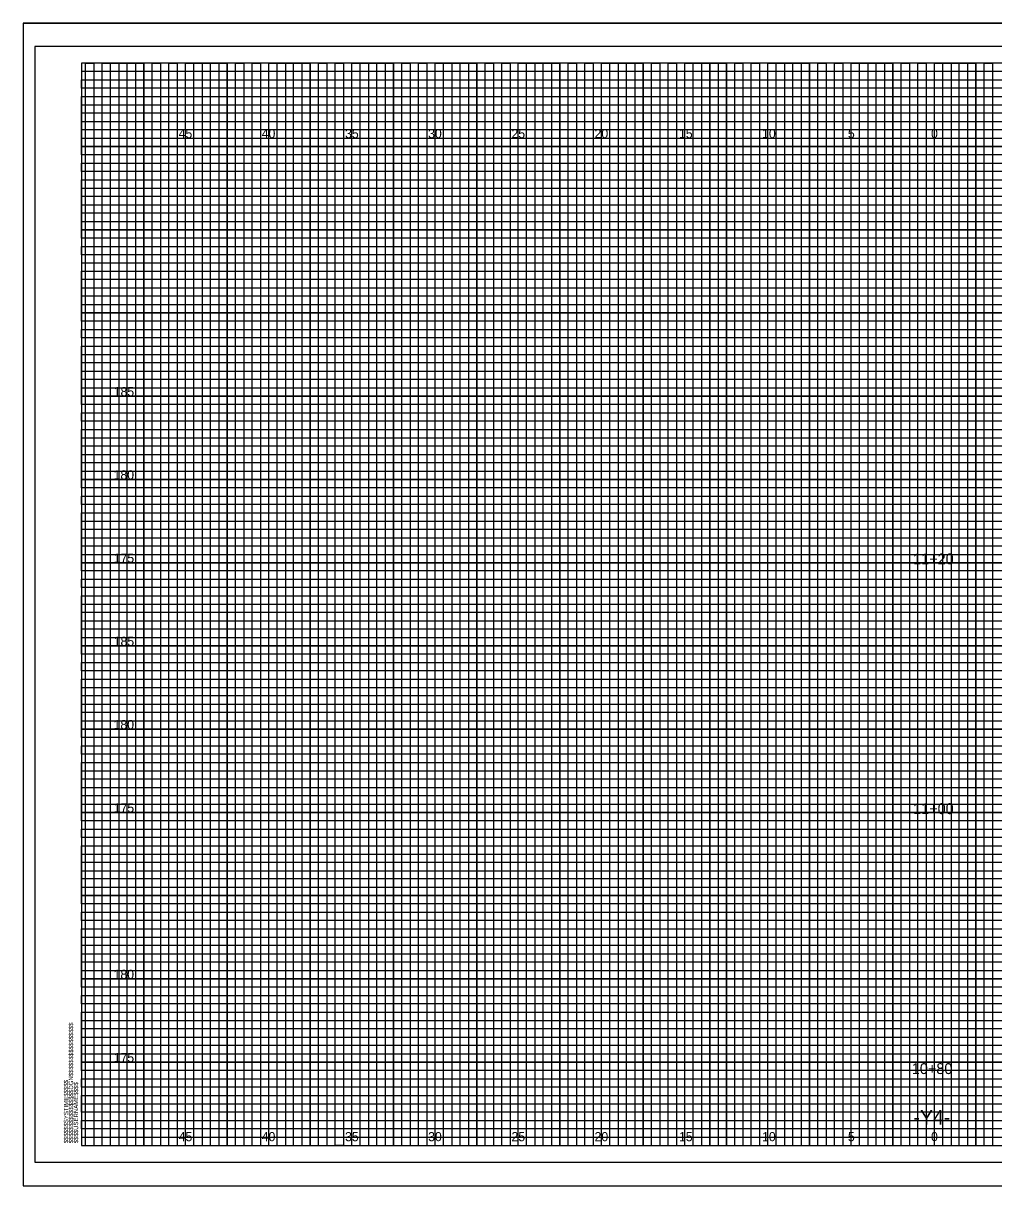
# Model space of a CAD drawing. Extents: x -4 to 103, y -2 to 138.
# Drawn here: x -3.5 to 54.8, y 68.4 to 138.2 of the extents above; entities that cross this region are included whole.
import ezdxf

# ---------------------------------------------------------------- set-up
doc = ezdxf.new("R2010")
doc.units = 0
for name, color, linetype in [('Old_Level_10', 7, 'Continuous'), ('Old_Level_3', 7, 'Continuous'), ('Old_Level_4', 7, 'Continuous'), ('Old_Level_5', 7, 'Continuous'), ('Old_Level_8', 7, 'Continuous'), ('Prop XS Dump Level', 7, 'Continuous'), ('Prop XS Elevation Labels', 7, 'Continuous'), ('Prop XS EOT Tick Mark', 7, 'Continuous'), ('Prop XS Finish Grade', 7, 'Continuous'), ('Prop XS Finish Grade Pavement', 7, 'Continuous'), ('Prop XS Subgrade Concrete', 7, 'Continuous')]:
    doc.layers.add(name, color=color, linetype=linetype)

msp = doc.modelspace()

# ---------------------------------------------------------------- linework, layer by layer
at = {"layer": 'Old_Level_10'}
for p, q in [((1.25, 70.825), (1.25, 135.825)), ((3.75, 70.825), (3.75, 135.825)), ((6.25, 70.825), (6.25, 135.825)), ((8.75, 70.825), (8.75, 135.825)), ((11.25, 70.825), (11.25, 135.825)), ((13.75, 70.825), (13.75, 135.825)), ((16.25, 70.825), (16.25, 135.825)), ((18.75, 70.825), (18.75, 135.825)), ((21.25, 70.825), (21.25, 135.825)), ((23.75, 70.825), (23.75, 135.825)), ((26.25, 70.825), (26.25, 135.825)), ((28.75, 70.825), (28.75, 135.825)), ((31.25, 70.825), (31.25, 135.825)), ((33.75, 70.825), (33.75, 135.825)), ((36.25, 70.825), (36.25, 135.825)), ((38.75, 70.825), (38.75, 135.825)), ((41.25, 70.825), (41.25, 135.825)), ((43.75, 70.825), (43.75, 135.825)), ((46.25, 70.825), (46.25, 135.825)), ((48.75, 70.825), (48.75, 135.825)), ((51.25, 70.825), (51.25, 135.825)), ((53.75, 70.825), (53.75, 135.825)), ((0, 133.325), (74.25, 133.325)), ((0, 130.825), (102.5, 130.825)), ((0, 128.325), (102.5, 128.325)), ((0, 125.825), (102.5, 125.825)), ((0, 123.325), (102.5, 123.325)), ((0, 120.825), (102.5, 120.825)), ((0, 118.325), (102.5, 118.325)), ((0, 115.825), (102.5, 115.825)), ((0, 113.325), (102.5, 113.325)), ((0, 110.825), (102.5, 110.825)), ((0, 108.325), (102.5, 108.325)), ((0, 105.825), (102.5, 105.825)), ((0, 103.325), (102.5, 103.325)), ((0, 100.825), (102.5, 100.825)), ((0, 98.325), (102.5, 98.325)), ((0, 95.825), (102.5, 95.825)), ((0, 93.325), (102.5, 93.325)), ((0, 90.825), (102.5, 90.825)), ((0, 88.325), (102.5, 88.325)), ((0, 85.825), (102.5, 85.825)), ((0, 83.325), (102.5, 83.325)), ((0, 80.825), (102.5, 80.825)), ((0, 78.325), (102.5, 78.325)), ((0, 75.825), (102.5, 75.825)), ((0, 73.325), (102.5, 73.325))]:
    msp.add_line(p, q, dxfattribs=at)
at = {"layer": 'Old_Level_3'}
for p, q in [((-3.5, 138.225), (103.4, 138.225)), ((-3.5, 138.225), (-3.5, 68.4)), ((-3.5, 68.4), (103.4, 68.4))]:
    msp.add_line(p, q, dxfattribs=at)
at = {"layer": 'Old_Level_4'}
msp.add_lwpolyline([(103, 136.825), (-2.8, 136.825), (-2.8, 69.825), (103, 69.825)], close=True, dxfattribs=at)
at = {"layer": 'Old_Level_5'}
msp.add_lwpolyline([(103.4, 138.225), (-3.5, 138.225), (-3.5, 68.4), (103.4, 68.4)], close=True, dxfattribs=at)
at = {"layer": 'Old_Level_8'}
for points in [[(1.25, 70.825), (1.25, 135.825), (3.75, 135.825), (3.75, 70.825), (6.25, 70.825), (6.25, 135.825), (8.75, 135.825), (8.75, 70.825), (11.25, 70.825), (11.25, 135.825), (13.75, 135.825), (13.75, 70.825), (16.25, 70.825), (16.25, 135.825), (18.75, 135.825), (18.75, 70.825), (21.25, 70.825), (21.25, 135.825), (23.75, 135.825), (23.75, 70.825), (26.25, 70.825), (26.25, 135.825), (28.75, 135.825), (28.75, 70.825), (31.25, 70.825), (31.25, 135.825), (33.75, 135.825), (33.75, 70.825), (36.25, 70.825), (36.25, 135.825), (38.75, 135.825), (38.75, 70.825), (41.25, 70.825), (41.25, 135.825), (43.75, 135.825), (43.75, 70.825), (46.25, 70.825), (46.25, 135.825), (48.75, 135.825), (48.75, 70.825), (51.25, 70.825), (51.25, 135.825), (53.75, 135.825), (53.75, 70.825)], [(102.5, 130.825), (0, 130.825), (0, 133.325), (74.25, 133.325)], [(102.5, 125.825), (0, 125.825), (0, 128.325), (102.5, 128.325)], [(102.5, 120.825), (0, 120.825), (0, 123.325), (102.5, 123.325)], [(102.5, 115.825), (0, 115.825), (0, 118.325), (102.5, 118.325)], [(102.5, 110.825), (0, 110.825), (0, 113.325), (102.5, 113.325)], [(102.5, 105.825), (0, 105.825), (0, 108.325), (102.5, 108.325)], [(102.5, 100.825), (0, 100.825), (0, 103.325), (102.5, 103.325)], [(102.5, 95.825), (0, 95.825), (0, 98.325), (102.5, 98.325)], [(102.5, 90.825), (0, 90.825), (0, 93.325), (102.5, 93.325)], [(102.5, 85.825), (0, 85.825), (0, 88.325), (102.5, 88.325)], [(102.5, 80.825), (0, 80.825), (0, 83.325), (102.5, 83.325)], [(102.5, 75.825), (0, 75.825), (0, 78.325), (102.5, 78.325)], [(0, 73.325), (102.5, 73.325)]]:
    msp.add_lwpolyline(points, dxfattribs=at)
at = {"layer": 'Prop XS Elevation Labels'}
msp.add_lwpolyline([(102.5, 135.825), (0, 135.825), (0, 70.825), (102.5, 70.825)], close=True, dxfattribs=at)
at = {"layer": 'Prop XS Finish Grade'}
for points in [[(0.25, 70.825), (0.25, 135.825), (0.75, 135.825), (0.75, 70.825), (1.75, 70.825), (1.75, 135.825), (2.25, 135.825), (2.25, 70.825), (2.75, 70.825), (2.75, 135.825), (3.25, 135.825), (3.25, 70.825), (4.25, 70.825), (4.25, 135.825), (4.75, 135.825), (4.75, 70.825), (5.25, 70.825), (5.25, 135.825), (5.75, 135.825), (5.75, 70.825), (6.75, 70.825), (6.75, 135.825), (7.25, 135.825), (7.25, 70.825), (7.75, 70.825), (7.75, 135.825), (8.25, 135.825), (8.25, 70.825), (9.25, 70.825), (9.25, 135.825), (9.75, 135.825), (9.75, 70.825), (10.25, 70.825), (10.25, 135.825), (10.75, 135.825), (10.75, 70.825), (11.75, 70.825), (11.75, 135.825), (12.25, 135.825), (12.25, 70.825), (12.75, 70.825), (12.75, 135.825), (13.25, 135.825), (13.25, 70.825), (14.25, 70.825), (14.25, 135.825), (14.75, 135.825), (14.75, 70.825), (15.75, 70.825), (15.25, 70.825), (15.25, 135.825), (15.75, 135.825), (15.75, 70.825), (16.75, 70.825), (16.75, 135.825), (17.25, 135.825), (17.25, 70.825), (17.75, 70.825), (17.75, 135.825), (18.25, 135.825), (18.25, 70.825), (19.25, 70.825), (19.25, 135.825), (19.75, 135.825), (19.75, 70.825), (20.25, 70.825), (20.25, 135.825), (20.75, 135.825), (20.75, 70.825), (21.75, 70.825), (21.75, 135.825), (22.25, 135.825), (22.25, 70.825), (22.75, 70.825), (22.75, 135.825), (23.25, 135.825), (23.25, 70.825), (24.25, 70.825), (24.25, 135.825), (24.75, 135.825), (24.75, 70.825), (25.25, 70.825), (25.25, 135.825), (25.75, 135.825), (25.75, 70.825), (26.75, 70.825), (26.75, 135.825), (27.25, 135.825), (27.25, 70.825), (27.75, 70.825), (27.75, 135.825), (28.25, 135.825), (28.25, 70.825), (29.25, 70.825), (29.25, 135.825), (29.75, 135.825), (29.75, 70.825), (30.25, 70.825), (30.25, 135.825), (30.75, 135.825), (30.75, 70.825)], [(30.75, 70.825), (31.75, 70.825), (31.75, 135.825), (32.25, 135.825), (32.25, 70.825), (32.75, 70.825), (32.75, 135.825), (33.25, 135.825), (33.25, 70.825), (34.25, 70.825), (34.25, 135.825), (34.75, 135.825), (34.75, 70.825), (35.25, 70.825), (35.25, 135.825), (35.75, 135.825), (35.75, 70.825), (36.75, 70.825), (36.75, 135.825), (37.25, 135.825), (37.25, 70.825), (37.75, 70.825), (37.75, 135.825), (37.75, 70.825)], [(38.25, 135.825), (38.25, 70.825), (39.25, 70.825), (39.25, 135.825), (39.75, 135.825), (39.75, 70.825), (40.25, 70.825), (40.25, 135.825), (40.75, 135.825), (40.75, 70.825), (41.75, 70.825), (41.75, 135.825), (42.25, 135.825), (42.25, 70.825), (42.75, 70.825), (42.75, 135.825), (43.25, 135.825), (43.25, 70.825), (43.75, 70.825), (44.25, 70.825), (44.25, 135.825), (44.75, 135.825), (44.75, 70.825), (45.25, 70.825), (45.25, 135.825), (45.75, 135.825), (45.75, 70.825), (46.75, 70.825), (46.75, 135.825), (47.25, 135.825), (47.25, 70.825), (47.75, 70.825), (47.75, 135.825), (48.25, 135.825), (48.25, 70.825), (49.25, 70.825), (49.25, 135.825), (49.75, 135.825), (49.75, 70.825), (50.25, 70.825), (50.25, 135.825), (50.75, 135.825), (50.75, 70.825), (51.75, 70.825), (51.75, 135.825), (52.25, 135.825), (52.25, 70.825), (52.75, 70.825), (52.75, 135.825), (53.25, 135.825), (53.25, 70.825), (54.25, 70.825), (54.25, 135.825), (54.75, 135.825), (54.75, 70.825), (55.25, 70.825)], [(0, 132.825), (0, 133.825), (74.25, 133.825), (74.25, 134.325), (0, 134.325), (0, 134.825), (74.25, 134.825), (74.25, 135.325), (0, 135.325)], [(102.5, 132.825), (0, 132.825)], [(102.5, 131.825), (0, 131.825), (0, 132.325), (102.5, 132.325)], [(102.5, 130.325), (0, 130.325), (0, 131.325), (102.5, 131.325)], [(102.5, 129.325), (0, 129.325), (0, 129.825), (102.5, 129.825)], [(102.5, 127.825), (0, 127.825), (0, 128.825), (102.5, 128.825)], [(102.5, 126.825), (0, 126.825), (0, 127.325), (102.5, 127.325)], [(102.5, 125.325), (0, 125.325), (0, 126.325), (102.5, 126.325)], [(102.5, 124.325), (0, 124.325), (0, 124.825), (102.5, 124.825)], [(0, 123.825), (102.5, 123.825)], [(102.5, 122.825), (0, 122.825)], [(102.5, 121.825), (0, 121.825), (0, 122.325), (102.5, 122.325)], [(102.5, 120.325), (0, 120.325), (0, 121.325), (102.5, 121.325)], [(102.5, 119.325), (0, 119.325), (0, 119.825), (102.5, 119.825)], [(102.5, 117.825), (0, 117.825), (0, 118.825), (102.5, 118.825)], [(102.5, 116.825), (0, 116.825), (0, 117.325), (102.5, 117.325)], [(102.5, 115.325), (0, 115.325), (0, 116.325), (102.5, 116.325)], [(102.5, 114.325), (0, 114.325), (0, 114.825), (102.5, 114.825)], [(102.5, 112.825), (0, 112.825), (0, 113.825), (102.5, 113.825)], [(102.5, 111.825), (0, 111.825), (0, 112.325), (102.5, 112.325)], [(102.5, 110.325), (0, 110.325), (0, 111.325), (102.5, 111.325)], [(102.5, 109.325), (0, 109.325), (0, 109.825), (102.5, 109.825)], [(102.5, 107.825), (0, 107.825), (0, 108.825), (102.5, 108.825)], [(102.5, 106.825), (0, 106.825), (0, 107.325), (102.5, 107.325)], [(102.5, 105.325), (0, 105.325), (0, 106.325), (102.5, 106.325)], [(102.5, 104.325), (0, 104.325), (0, 104.825), (102.5, 104.825)], [(102.5, 102.825), (0, 102.825), (0, 103.825), (102.5, 103.825)], [(102.5, 101.825), (0, 101.825), (0, 102.325)], [(0, 102.325), (102.5, 102.325)], [(102.5, 100.325), (0, 100.325), (0, 101.325), (102.5, 101.325)], [(102.5, 99.325), (0, 99.325), (0, 99.825), (102.5, 99.825)], [(102.5, 97.825), (0, 97.825), (0, 98.825), (102.5, 98.825)], [(102.5, 96.825), (0, 96.825), (0, 97.325), (102.5, 97.325)], [(102.5, 95.325), (0, 95.325), (0, 96.325), (102.5, 96.325)], [(102.5, 94.325), (0, 94.325), (0, 94.825), (102.5, 94.825)], [(102.5, 92.825), (0, 92.825), (0, 93.825), (102.5, 93.825)], [(102.5, 91.825), (0, 91.825), (0, 92.325), (102.5, 92.325)], [(102.5, 90.325), (0, 90.325), (0, 91.325), (102.5, 91.325)], [(102.5, 89.325), (0, 89.325), (0, 89.825), (102.5, 89.825)], [(102.5, 87.825), (0, 87.825), (0, 88.825), (102.5, 88.825)], [(102.5, 86.825), (0, 86.825), (0, 87.325), (102.5, 87.325)], [(102.5, 85.325), (0, 85.325), (0, 86.325), (102.5, 86.325)], [(102.5, 84.325), (0, 84.325), (0, 84.825), (102.5, 84.825)], [(102.5, 82.825), (0, 82.825), (0, 83.825), (102.5, 83.825)], [(102.5, 81.825), (0, 81.825), (0, 82.325), (102.5, 82.325)], [(102.5, 80.325), (0, 80.325), (0, 81.325), (102.5, 81.325)], [(102.5, 79.325), (0, 79.325), (0, 79.825), (102.5, 79.825)], [(102.5, 77.825), (0, 77.825), (0, 78.825), (102.5, 78.825)], [(102.5, 76.825), (0, 76.825), (0, 77.325), (102.5, 77.325)], [(102.5, 75.325), (0, 75.325), (0, 76.325), (102.5, 76.325)], [(102.5, 74.325), (0, 74.325), (0, 74.825), (102.5, 74.825)], [(102.5, 72.825), (0, 72.825), (0, 73.825), (102.5, 73.825)], [(102.5, 71.825), (0, 71.825), (0, 72.325), (102.5, 72.325)], [(0, 71.325), (102.5, 71.325)]]:
    msp.add_lwpolyline(points, dxfattribs=at)

# ---------------------------------------------------------------- texts
at = {"layer": 'Old_Level_8'}
msp.add_text('040397', height=0.0025, rotation=90, dxfattribs=at).set_placement((-0.001, 135.811))
at = {"layer": 'Prop XS Dump Level'}
for s, p in [('11+20', (49.971, 105.724)), ('11+00', (49.971, 90.724)), ('10+80', (49.893, 75.11))]:
    msp.add_text(s, height=0.65, dxfattribs=at).set_placement(p)
at = {"layer": 'Prop XS Elevation Labels'}
for s, p in [('$$$$$$$$$$$$$$$$DGN$$$$$$$$$$$$$$$$', (-0.5, 70.95)), ('$$$$$$SYSTIME$$$$$', (-0.797, 70.95)), ('$$$$USERNAME$$$$', (-0.2, 70.95))]:
    msp.add_text(s, height=0.2625, rotation=90, dxfattribs=at).set_placement(p)
at = {"layer": 'Prop XS EOT Tick Mark'}
for s, p in [('185', (1.938, 115.825)), ('180', (1.93, 110.825)), ('175', (1.938, 105.825)), ('185', (1.938, 100.825)), ('180', (1.93, 95.825)), ('175', (1.938, 90.825)), ('180', (1.93, 80.825)), ('175', (1.938, 75.825))]:
    msp.add_text(s, height=0.55, dxfattribs=at).set_placement(p)
at = {"layer": 'Prop XS Finish Grade Pavement'}
for s, p in [('45', (5.84, 131.325)), ('40', (10.831, 131.325)), ('35', (15.84, 131.325)), ('30', (20.831, 131.325)), ('25', (25.84, 131.325)), ('20', (30.831, 131.325)), ('15', (35.906, 131.325)), ('10', (40.897, 131.325)), ('5', (46.057, 131.325)), ('0', (51.049, 131.325)), ('0', (51.049, 131.325)), ('45', (5.84, 71.075)), ('40', (10.831, 71.075)), ('35', (15.84, 71.075)), ('30', (20.831, 71.075)), ('25', (25.84, 71.075)), ('20', (30.831, 71.075)), ('15', (35.906, 71.075)), ('10', (40.897, 71.075)), ('5', (46.057, 71.075)), ('0', (51.049, 71.075)), ('0', (51.049, 71.075))]:
    msp.add_text(s, height=0.55, dxfattribs=at).set_placement(p)
at = {"layer": 'Prop XS Subgrade Concrete'}
msp.add_text('-Y4-', height=0.875, dxfattribs=at).set_placement((49.998, 72.075))

doc.saveas('drawing.dxf')
